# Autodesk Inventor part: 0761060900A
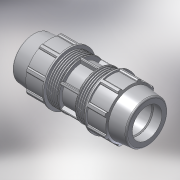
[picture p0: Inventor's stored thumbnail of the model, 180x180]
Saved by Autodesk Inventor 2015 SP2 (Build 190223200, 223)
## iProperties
Created: 2017-02
Part Number: 0761060900A
Material: PVC-Piping
Description: PLASSON REPAIR COUPLER 90
Document SubType Name: Modeling
Designer: KIM
Mass: 2387.75 g
Surface Area: 2478.17 cm^2
Volume: 1705.54 cm^3
Density: 1.4 g/cm^3
Appearance: Smooth - White
Author: KIM
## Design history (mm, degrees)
derived "87610.ipt"
feature "Solid1::87610.ipt"
tag "TaggingFeature1"
body "Solid1"
other parameters: "d1" = 335, "d4" = 27.91667, "d5" = 47.85714, "d7" = 154, "d8" = 115.5, "d9" = 47.85714, "d11" = 4.78571, "d12" = 123.2, "d13" = 120 deg, "d14" = 117, "d15" = 6 deg, "d16" = 138.6, "d18" = 4.5, "d19" = 35 deg, "d20" = 17.5 deg, "d21" = 143.22, "d23" = 0, "d25" = 360 deg, "d27" = 3.08, "d33" = 1.8, "d34" = 7.7, "d36" = 0, "d37" = 1.8, "d38" = 1.8, "d40" = 360 deg, "d42" = 60.3, "d46" = 2.7, "d50" = 4.1875, "d51" = 0, "d53" = 3.06286, "d54" = 3.06286, "d57" = 6.12571, "d62" = 135.828, "E_" = 154, "H_" = 335, "l_" = 143, "d52" = 30.62857
